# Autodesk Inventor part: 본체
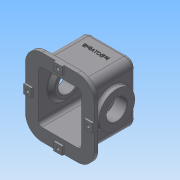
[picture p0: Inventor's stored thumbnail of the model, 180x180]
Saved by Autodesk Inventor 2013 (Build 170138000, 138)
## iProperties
Created: 2014-11
Part Number: 본체
Material: 일반
Document SubType Name: Modeling
Designer: Administrator
Density: 1 g/cm^3
Author: Administrator
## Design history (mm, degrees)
sketch "스케치1"
  geometry: L1 (-65, 64)-(65, 64); L2 (65, 64)-(65, -64); L3 (65, -64)-(-65, -64); L4 (-65, -64)-(-65, 64); L5 (-65, 64)-(65, -64); L6 (65, 64)-(-65, -64); 1 further point
  constraints: 12 end point, 2 midpoint, 2 parallel, 1 horizontal, 1 perpendicular
  dimensions: "d0" = 130 distance of L2.end L3.end; "d1" = 128 distance of L1.end L2.end
extrude "돌출1" new body sketch "스케치1" stored distance "d2" = 152; taper "d3" = 0 deg
sketch "스케치2"
  geometry: L1 (130, 0)-(130, -152) reference; L2 (0, 0)-(130, 0) reference; L3 (0, 0)-(0, -152) reference; L4 (130, -152)-(0, -152) reference; L5 (-22, 22)-(152, 22); L6 (152, 22)-(152, -174); L7 (152, -174)-(-22, -174); L8 (-22, -174)-(-22, 22); L9 (-22, 22)-(152, -174); L10 (152, 22)-(-22, -174); 1 further point
  constraints: 12 end point, 2 midpoint, 2 parallel, 1 horizontal, 1 perpendicular
  dimensions: "d4" = 174 distance of L6.end L7.end; "d6" = 196 distance of L5.end L6.end
extrude "돌출2" join sketch "스케치2" distance "d7" = 10; taper "d8" = 0 deg
fillet "모깎기1" dims "d27" = 10
fillet "모깎기2" dims "d28" = 20
fillet "모깎기3" dims "d29" = 42
feature "쉘1" dims "d30" = 10
sketch "스케치7"
  geometry: L1 (0, -10)-(112, -10) reference; C1 r 45.5 at (56, 58); 1 further point
  constraints: 1 centre point, 1 coincident
  dimensions: "d42" = 91 diameter of C1; "d126" = 68 distance from line of L1 point (56, 58)
extrude "돌출5" join sketch "스케치7" distance "d43" = 12; taper "d44" = 0 deg
sketch "스케치8"
  geometry: C1 r 45.5 at (0, 0) reference; C2 r 26 at (0, 0)
  constraints: 1 centre point, 1 coincident
  dimensions: "d45" = 52 diameter of C2
extrude "돌출6" cut sketch "스케치8" distance "d46" = 32; taper "d47" = 0 deg
sketch "스케치9" dims "d48" = 70
  geometry: C1 r 45.5 at (0, 0) reference; 2 further points
  constraints: 2 vertical alignment, 1 coincident, 2 other
hole "구멍3" sketch "스케치9" at (0, 35) diameter "d49" = 3.242; stored, may be unused: countersink angle "d53" = 90 deg, drill point angle "d55" = 118 deg; dims "d50" = 13, "d51" = 4, "d52" = 2, "d54" = 16
sketch "스케치10"
  geometry: L1 (45, 54)-(55, 54) reference; L2 (55, -64)-(55, 54) reference; L3 (45, -64)-(55, -64) reference; L4 (45, 54)-(45, -64) reference; L5 (77, -41.5)-(65, -41.5) reference; L6 (65, -41.5)-(65, -54) reference; L7 (65, -54)-(87, -54) reference; L8 (87, -54)-(87, -64) reference; L9 (87, -64)-(55, -64) reference; L10 (55, -64)-(55, -22) reference; L11 (55, -22)-(77, -22) reference; L12 (77, -22)-(77, -29.379) reference; L13 (77, -29.379)-(61, -29.379) reference; L14 (61, -29.379)-(60.026, -31) reference; L15 (60.026, -31)-(61, -32.621) reference; L16 (61, -32.621)-(77, -32.621) reference; L17 (77, -32.621)-(77, -41.5) reference; L18 (65, 54)-(65, 49.5) reference; L19 (65, 49.5)-(77, 49.5) reference; L20 (77, 49.5)-(77, 40.621) reference; L21 (77, 40.621)-(61, 40.621) reference; L22 (61, 40.621)-(60.026, 39) reference; L23 (60.026, 39)-(61, 37.379) reference; L24 (61, 37.379)-(77, 37.379) reference; L25 (77, 37.379)-(77, 30) reference; L26 (77, 30)-(55, 30) reference; L27 (55, 30)-(55, 54) reference; L28 (55, 54)-(-55, 54) reference; L29 (-55, 54)-(-55, -64) reference; L30 (-55, -64)-(-87, -64) reference; L31 (-87, -64)-(-87, -54) reference; L32 (-87, -54)-(-65, -54) reference; L33 (-65, -54)-(-65, 54) reference; L34 (-55, 64)-(55, 64) reference; L35 (45, 39.5)-(45, 4); L36 (77, 30)-(77, -22) reference; L37 (45, 4)-(55, 4); L38 (45, 39.5)-(55, 49.5); A1 r 10 centre (55, 54) between (65, 54) and (55, 64) reference; A2 r 10 centre (-55, 54) between (-55, 64) and (-65, 54) reference; 2 further points
  constraints: 6 end point, 2 point on line, 1 horizontal alignment, 1 midpoint, 1 parallel, 1 perpendicular
  dimensions: "d127" = 10 distance of L35.end L37.end; "d130" = 91 diameter of L38.end L37; "d131" = 71 diameter of L35.start L37
  node "투영된 루프1"
  node "절단 모서리 투영1"
node "작업 평면1"
chamfer "모따기1" distance "d69" = 1; stored, may be unused: second distance "d70" = 2, angle "d71" = 45 deg
fillet "모깎기4" dims "d72" = 3
fillet "모깎기5" dims "d79" = 3
node "작업 평면2"
node "작업 평면3"
sketch "스케치16"
  geometry: L1 (-22, 132)-(-22, 20) reference; C1 r 7 at (-12, 76); 3 further points
  constraints: 1 centre point, 1 coincident, 1 horizontal alignment, 1 midpoint
  dimensions: "d95" = 14 diameter of C1; "d96" = 10 distance from line of C1.centre L1
hole "구멍4" sketch "스케치16" at (-12, 76) diameter "d97" = 9; stored, may be unused: countersink angle "d101" = 90 deg, drill point angle "d103" = 0 deg; dims "d98" = 50, "d99" = 14, "d100" = 8.6, "d102" = 20
sketch "스케치17"
  geometry: L1 (20, -22)-(110, -22) reference; 3 further points
  constraints: 1 midpoint, 1 vertical alignment
  dimensions: "d104" = 10 distance from line of L1 point (65, -12)
hole "구멍5" sketch "스케치17" at (65, -12) diameter "d105" = 9; stored, may be unused: countersink angle "d109" = 90 deg, drill point angle "d111" = 0 deg; dims "d106" = 50, "d107" = 14, "d108" = 8.6, "d110" = 20
sketch "스케치18"
  geometry: L1 (112, 87)-(132, 87); L2 (132, 87)-(132, 109); L3 (132, 109)-(112, 109); L4 (112, 109)-(112, 87); L5 (112, 87)-(132, 109); L6 (132, 87)-(112, 109); C1 r 4.5 at (122, 98) reference; 1 further point
  constraints: 12 end point, 2 midpoint, 2 parallel, 1 horizontal, 1 perpendicular
  dimensions: "d112" = 20 distance of L3.end L2.end; "d113" = 22 distance of L1.end L2.end
extrude "돌출12" join sketch "스케치18" distance "d114" = 5; taper "d115" = 0 deg
sketch "스케치19"
  geometry: L1 (34, 20)-(56, 20); L2 (56, 20)-(56, 0); L3 (56, 0)-(34, 0); L4 (34, 0)-(34, 20); L5 (34, 20)-(56, 0); L6 (56, 20)-(34, 0); C1 r 4.5 at (45, 10) reference; 1 further point
  constraints: 12 end point, 2 midpoint, 2 parallel, 1 horizontal, 1 perpendicular
  dimensions: "d116" = 22 distance of L2.end L3.end; "d117" = 20 distance of L1.end L2.end
extrude "돌출13" join sketch "스케치19" distance "d118" = 5; taper "d119" = 0 deg
fillet "모깎기8" dims "d120" = 3
fillet "모깎기10" dims "d122" = 3
sketch "스케치20"
  geometry: L1 (-45, -64)-(-11, -64) reference; 2 further points
  constraints: 1 vertical alignment, 1 other
  dimensions: "d123" = 92 distance from line of L1 point (0, 28)
revolve "회전2" stored, may be unused: angle "d132" = 90 deg
sketch "스케치21"
  geometry: C1 r 35.5 at (0, 0) reference; C2 r 26 at (0, 0); 1 further point
  constraints: 1 centre point, 1 coincident
  dimensions: "d133" = 52 diameter of C2
extrude "돌출14" cut sketch "스케치21" stored distance "d134" = 10; taper "d135" = 0 deg
sketch "스케치22"
  geometry: C1 r 35.5 at (0, 0) reference; C2 r 26 at (0, 0); 1 further point
  constraints: 1 centre point, 1 concentric
  dimensions: "d136" = 52 diameter of C2
extrude "돌출15" cut sketch "스케치22" stored distance "d137" = 10; taper "d138" = 0 deg
sketch "스케치23"
  geometry: L1 (64, 18.939)-(94.566, 12.442); L2 (94.566, 12.442)-(81.675, -48.203); L3 (81.675, -48.203)-(64, -44.446); L4 (-62.6, -92.5)-(-62.6, -95) reference; L5 (-62.6, -95)-(-54, -95) reference; L6 (-54, -95)-(-54, -98) reference; L7 (-54, -98)-(-69, -98) reference; L8 (-69, -98)-(-69, -92.5) reference; L9 (-69, -92.5)-(-62.6, -92.5) reference; L10 (-62.6, 95)-(-62.6, 92.5) reference; L11 (-62.6, 92.5)-(-69, 92.5) reference; L12 (-69, 92.5)-(-69, 98) reference; L13 (-69, 98)-(-54, 98) reference; L14 (-54, 98)-(-54, 95) reference; L15 (-54, 95)-(-62.6, 95) reference; L16 (64, 66)-(64, -66) reference; L17 (54, -76)-(-51, -76) reference; L18 (-54, -79)-(-54, -81) reference; L19 (-54, -81)-(-62.6, -81) reference; L20 (-62.6, -81)-(-62.6, -83.5) reference; L21 (-62.6, -83.5)-(-69, -83.5) reference; L22 (-69, -83.5)-(-69, -78) reference; L23 (-69, -78)-(-64, -78) reference; L24 (-64, -78)-(-64, -66) reference; L25 (-64, -66)-(51, -66) reference; L26 (54, -63)-(54, 63) reference; L27 (51, 66)-(-64, 66) reference; L28 (-64, 66)-(-64, 78) reference; L29 (-64, 78)-(-69, 78) reference; L30 (-69, 78)-(-69, 83.5) reference; L31 (-69, 83.5)-(-62.6, 83.5) reference; L32 (-62.6, 83.5)-(-62.6, 81) reference; L33 (-62.6, 81)-(-54, 81) reference; L34 (-54, 81)-(-54, 79) reference; L35 (-51, 76)-(54, 76) reference; L36 (4, 0)-(88.121, -17.88); L37 (-62.6, -92.5)-(-62.6, -95) reference; L38 (-62.6, -95)-(-54, -95) reference; L39 (-54, -95)-(-54, -98) reference; L40 (-54, -98)-(-69, -98) reference; L41 (-69, -98)-(-69, -92.5) reference; L42 (-69, -92.5)-(-62.6, -92.5) reference; L43 (-62.6, 95)-(-62.6, 92.5) reference; L44 (-62.6, 92.5)-(-69, 92.5) reference; L45 (-69, 92.5)-(-69, 98) reference; L46 (-69, 98)-(-54, 98) reference; L47 (-54, 98)-(-54, 95) reference; L48 (-54, 95)-(-62.6, 95) reference; L49 (64, 66)-(64, -66) reference; L50 (54, -76)-(-51, -76) reference; L51 (-54, -79)-(-54, -81) reference; L52 (-54, -81)-(-62.6, -81) reference; L53 (-62.6, -81)-(-62.6, -83.5) reference; L54 (-62.6, -83.5)-(-69, -83.5) reference; L55 (-69, -83.5)-(-69, -78) reference; L56 (-69, -78)-(-64, -78) reference; L57 (-64, -78)-(-64, -66) reference; L58 (-64, -66)-(51, -66) reference; L59 (54, -63)-(54, 63) reference; L60 (51, 66)-(-64, 66) reference; L61 (-64, 66)-(-64, 78) reference; L62 (-64, 78)-(-69, 78) reference; L63 (-69, 78)-(-69, 83.5) reference; L64 (-69, 83.5)-(-62.6, 83.5) reference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; C1 r 26 at (4, 0) reference; A1 r 10 centre (54, -66) between (54, -76) and (64, -66) reference; A2 r 3 centre (-51, -79) between (-51, -76) and (-54, -79) reference; A3 r 3 centre (51, -63) between (51, -66) and (54, -63) reference; A4 r 3 centre (51, 63) between (54, 63) and (51, 66) reference; A5 r 3 centre (-51, 79) between (-54, 79) and (-51, 76) reference; A6 r 10 centre (54, 66) between (64, 66) and (54, 76) reference; A7 r 10 centre (54, -66) between (54, -76) and (64, -66) reference; A8 r 3 centre (-51, -79) between (-51, -76) and (-54, -79) reference; A9 r 3 centre (51, -63) between (51, -66) and (54, -63) reference; A10 r 3 centre (51, 63) between (54, 63) and (51, 66) reference; A11 r 3 centre (-51, 79) between (-54, 79) and (-51, 76) reference; A12 r 10 centre (54, 66) between (64, 66) and (54, 76) reference
  constraints: 8 end point, 2 parallel, 2 point on line, 1 coincident, 1 midpoint, 1 perpendicular
  dimensions: "d139" = 12 deg angle of L27 L36; "d140" = 62 distance of L1.end L2.end; "d142" = 86 distance from line of L36.start L2
extrude "돌출16" join sketch "스케치23" stored distance "d143" = 62; taper "d144" = 0 deg
fillet "모깎기11" dims "d145" = 31
sketch "스케치24"
  geometry: C1 r 31 at (0, 0) reference; 1 further point
  constraints: 1 coincident
hole "구멍6" sketch "스케치24" at (0, 0) diameter "d146" = 30; stored, may be unused: countersink angle "d150" = 90 deg, drill point angle "d152" = 118 deg; dims "d147" = 6, "d148" = 42, "d149" = 25, "d151" = 50
fillet "모깎기12" dims "d153" = 3
fillet "모깎기13" dims "d154" = 0.3
fillet "모깎기14" dims "d155" = 3
chamfer "모따기3" distance "d156" = 1; stored, may be unused: second distance "d157" = 2, angle "d158" = 45 deg
feature "엠보싱2" dims "d4" = 174, "d6" = 196, "d159" = 1, "d160" = 0
node "솔리드1"
pattern_circular "원형 패턴3" dims angle "d57" = 360 deg
mirror "대칭3"
mirror "대칭4"
mirror "대칭5"
mirror "대칭6"
mirror "대칭7"
mirror "대칭8"
mirror "대칭9"
node "절단 모서리 투영3"
node "절단 모서리 투영4"
